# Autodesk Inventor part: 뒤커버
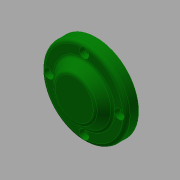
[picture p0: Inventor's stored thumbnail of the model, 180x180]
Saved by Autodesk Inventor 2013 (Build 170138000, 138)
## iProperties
Created: 2017-08
Part Number: 뒤커버
Material: 알루미늄 6061
Document SubType Name: Modeling
Designer: mduedu
Density: 1 g/cm^3
Author: mduedu
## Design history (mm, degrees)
sketch "스케치1"
  geometry: C1 r 35 at (0, 0); 1 further point
  constraints: 1 centre point, 1 coincident
  dimensions: "d0" = 70 diameter of C1
extrude "돌출1" new body sketch "스케치1" distance "d1" = 8; taper "d2" = 0 deg
sketch "스케치2"
  geometry: C1 r 24 at (0, 0); 1 further point
  constraints: 1 centre point, 1 coincident
  dimensions: "d3" = 48 diameter of C1
node "작업 평면1"
sketch "스케치3"
  geometry: C1 r 17 at (0, 0); 1 further point
  constraints: 1 centre point, 1 coincident
  dimensions: "d5" = 34 diameter of C1
feature "로프트1" sketch "스케치3" dims "d6" = 0, "d7" = 90 deg, "d8" = 0, "d9" = 90 deg
sketch "스케치4"
  geometry: C1 r 24 at (0, 0) reference; 1 further point
extrude "돌출2" join sketch "스케치4" distance "d10" = 8; taper "d11" = 0 deg
hole "구멍1" diameter "d14" = 40; stored, may be unused: countersink angle "d18" = 90 deg, drill point angle "d20" = 0 deg; dims "d12" = 10, "d13" = 10, "d15" = 6, "d16" = 4, "d17" = 2, "d19" = 12
hole "구멍2" diameter "d23" = 34; stored, may be unused: countersink angle "d27" = 90 deg, drill point angle "d29" = 0 deg; dims "d24" = 6, "d25" = 4, "d26" = 2, "d28" = 6, "d62" = 10, "d63" = 10
chamfer "모따기1" distance "d39" = 1; stored, may be unused: second distance "d40" = 2, angle "d41" = 45 deg
fillet "모깎기1" dims "d42" = 0.3
fillet "모깎기2" dims "d43" = 3
sketch "스케치5" dims "d44" = 58
  geometry: 6 further points
  constraints: 2 vertical alignment, 1 coincident, 7 other
  dimensions: "d47" = 360 deg dimension on point (0, 0) point (0, 29) (derived)
sketch "스케치6" dims "d64" = 58 (derived)
  geometry: 6 further points
  constraints: 1 coincident, 1 vertical alignment, 6 other
hole "구멍4" sketch "스케치6" at (0, 29), (-29, 0), (29, 0), (0, -29) diameter "d49" = 4.5; stored, may be unused: countersink angle "d53" = 90 deg, drill point angle "d55" = 0 deg; dims "d50" = 6, "d51" = 8, "d52" = 4.6, "d54" = 8
fillet "모깎기3" dims "d56" = 3
fillet "모깎기4" dims "d57" = 3
fillet "모깎기5" dims "d58" = 3
node "솔리드1"
other parameters: "d4" = 8
